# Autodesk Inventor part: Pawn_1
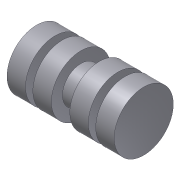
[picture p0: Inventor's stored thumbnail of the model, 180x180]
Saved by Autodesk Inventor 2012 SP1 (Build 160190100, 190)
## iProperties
Created: 2006-03
Part Number: Pawn_1
Document SubType Name: Modeling
Material: Stainless Steel, 440C
Mass: 36.6428 g
Surface Area: 24.2531 cm^2
Volume: 4.7281 cm^3
Density: 7.75 g/cm^3
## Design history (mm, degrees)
sketch "Sketch1"
  geometry: L1 (0, 0)-(2.5, 0); L2 (2.5, 0)-(2.5, 5); L3 (2.5, 5)-(0, 5); L4 (0, 5)-(0, 0); L5 (2.5, 8)-(7.5, 8); L6 (7.5, 8)-(7.5, 0); L7 (7.5, 0)-(2.5, 0); L8 (2.5, 0)-(2.5, 8); L9 (7.5, 5)-(9.5, 5); L10 (9.5, 5)-(9.5, 0); L11 (9.5, 0)-(7.5, 0); L12 (7.5, 0)-(7.5, 5); L13 (-4.35, 0)-(15.95, 0) reference; L14 (9.5, 8)-(14.5, 8); L15 (14.5, 8)-(14.5, 0); L16 (14.5, 0)-(9.5, 0); L17 (9.5, 0)-(9.5, 8)
  constraints: 32 end point, 8 parallel, 7 collinear, 4 horizontal, 4 perpendicular, 1 point on line
  dimensions: "d0" = 2.5 distance of L2.end L3.end; "d1" = 5 distance of L3.end L1.start; "d2" = 8 distance between parallel lines of L13 L5; "d3" = 2 distance of L9.start L9.end; "d4" = 5 distance of L14.start L14.end; "d5" = 5 distance between parallel lines of L9 L13
revolve "Revolution1" sketch "Sketch1" stored, may be unused: angle "d6" = 90 deg
mirror "Mirror1"
body "Solid1"
